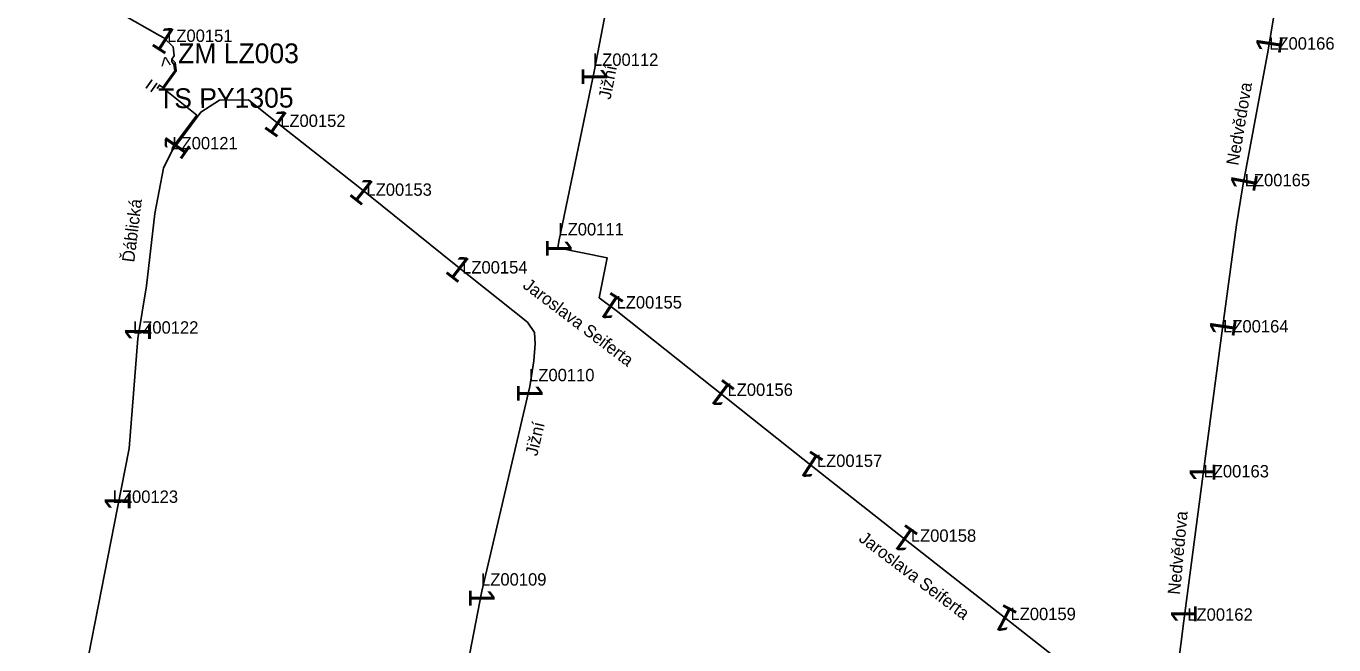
# Model space of a CAD drawing. Extents: x -736540 to -735418, y -1033000 to -1031598.
# Drawn here: x -735899.6 to -735635.6, y -1032780 to -1032655 of the extents above; entities that cross this region are included whole.
import ezdxf

# ---------------------------------------------------------------- set-up
doc = ezdxf.new("R2010")
doc.units = 0
for name, color, linetype in [('ftf_2010', 7, 'Continuous'), ('ftf_2060', 7, 'Continuous'), ('ftf_3010', 7, 'Continuous'), ('ftf_3010_ftf_3010_gtda_3015_gtda_3015_1', 7, 'Continuous'), ('ftf_3150', 7, 'Continuous'), ('ftf_3150_ftf_3150_gtda_3155_gtda_3155_1', 7, 'Continuous'), ('ftf_3160', 7, 'Continuous'), ('ftf_3160_ftf_3160_gtda_3165_gtda_3165_1', 7, 'Continuous'), ('ftf_nu', 7, 'Continuous')]:
    doc.layers.add(name, color=color, linetype=linetype)

msp = doc.modelspace()

# ---------------------------------------------------------------- linework, layer by layer
at = {"layer": 'ftf_2010'}
for points in [[(-735644.46, -1032633.53), (-735648.88, -1032659.9)], [(-735787.44, -1032639.95), (-735782.6, -1032651.92), (-735784.87, -1032663.88)], [(-735899.61, -1032641.58), (-735872.69, -1032656.96)], [(-735872.69, -1032656.96), (-735871.81, -1032657.37), (-735869.91, -1032659.24), (-735869.7, -1032661.03), (-735870.21, -1032661.69)], [(-735648.88, -1032659.9), (-735654.04, -1032687.7)], [(-735870.21, -1032661.69), (-735869.54, -1032662.38), (-735869.3, -1032664.04), (-735871.9, -1032667.64), (-735868.54, -1032670.33), (-735865.18, -1032673.02), (-735870.05, -1032679.55), (-735870.2, -1032680.32)], [(-735792.09, -1032698.53), (-735784.87, -1032663.88)], [(-735870.2, -1032680.32), (-735864.37, -1032672.38), (-735860.55, -1032670), (-735854.75, -1032669.95), (-735849.92, -1032673.73)], [(-735832.6, -1032687.44), (-735849.92, -1032673.73)], [(-735870.2, -1032680.32), (-735871.88, -1032683.75), (-735873.65, -1032692.87), (-735875.34, -1032707.51), (-735877.04, -1032718.13)], [(-735813.21, -1032703.05), (-735832.6, -1032687.44)], [(-735654.04, -1032687.7), (-735655.25, -1032695.17), (-735658.23, -1032717.05)], [(-735792.09, -1032698.53), (-735792.3, -1032699.81), (-735782.31, -1032701.83), (-735783.9, -1032709.89), (-735780.53, -1032712.49)], [(-735813.21, -1032703.05), (-735798.38, -1032714.84), (-735796.99, -1032716.9), (-735796.84, -1032719.22), (-735797.09, -1032722.59), (-735797.94, -1032727.81)], [(-735758.24, -1032730.13), (-735780.53, -1032712.49)], [(-735881.14, -1032752.3), (-735878.85, -1032740.32), (-735877.04, -1032718.13)], [(-735658.23, -1032717.05), (-735662.14, -1032746.47)], [(-735797.94, -1032727.81), (-735807.64, -1032769.14)], [(-735740.2, -1032744.51), (-735758.24, -1032730.13)], [(-735721.18, -1032759.43), (-735740.2, -1032744.51)], [(-735662.14, -1032746.47), (-735665.87, -1032775.1)], [(-735890.13, -1032800.57), (-735887.02, -1032782.2), (-735881.14, -1032752.3)], [(-735721.18, -1032759.43), (-735700.9, -1032775.41)], [(-735814.42, -1032804.25), (-735807.64, -1032769.14)], [(-735681.54, -1032790.25), (-735682.02, -1032790.23), (-735700.9, -1032775.41)], [(-735665.87, -1032775.1), (-735669.61, -1032804.33)]]:
    msp.add_lwpolyline(points, dxfattribs=at)
at = {"layer": 'ftf_2060'}
msp.add_lwpolyline([(-735870.22, -1032661.74), (-735870.17, -1032662.25), (-735869.79, -1032662.71), (-735869.62, -1032664.07), (-735872.02, -1032667.44), (-735872.71, -1032666.96), (-735873.19, -1032667.63)], dxfattribs=at)

# ---------------------------------------------------------------- texts
at = {"layer": 'ftf_3010'}
for rotation, p in [(327.2351, (-735874.64, -1032658.8)), (81.4163, (-735646.41, -1032660.93)), (270, (-735787.47, -1032663.23)), (325.0729, (-735851.94, -1032675.49)), (55.1966, (-735868.44, -1032682.34)), (321.395, (-735834.73, -1032689.06)), (79.2469, (-735651.6, -1032688.82)), (270, (-735794.69, -1032697.88)), (322.2711, (-735815.32, -1032704.71)), (146.9171, (-735778.57, -1032710.66)), (90, (-735874.44, -1032718.77)), (81.6782, (-735655.75, -1032718.07)), (143.1501, (-735756.16, -1032728.44)), (270, (-735800.54, -1032727.17)), (147.1474, (-735738.24, -1032742.68)), (90, (-735659.54, -1032747.12)), (90, (-735878.54, -1032752.95)), (144.8552, (-735719.15, -1032757.67)), (270, (-735810.24, -1032768.5)), (152.5559, (-735699.13, -1032773.4)), (90, (-735663.27, -1032775.75))]:
    msp.add_text('1', height=5.2, rotation=rotation, dxfattribs=at).set_placement(p)
at = {"layer": 'ftf_3010_ftf_3010_gtda_3015_gtda_3015_1'}
for s, p in [('LZ00151', (-735871.15, -1032658.23)), ('LZ00166', (-735648.66, -1032659.79)), ('LZ00152', (-735848.33, -1032675.39)), ('LZ00165', (-735653.6, -1032687.38)), ('LZ00153', (-735830.91, -1032689.3)), ('LZ00154', (-735811.59, -1032704.99)), ('LZ00155', (-735780.42, -1032712.06)), ('LZ00164', (-735657.96, -1032716.9)), ('LZ00156', (-735758.02, -1032729.7)), ('LZ00157', (-735739.98, -1032744.04)), ('LZ00163', (-735661.91, -1032746.16)), ('LZ00158', (-735721.01, -1032759.16)), ('LZ00159', (-735700.89, -1032774.98)), ('LZ00162', (-735665.19, -1032775.1))]:
    msp.add_text(s, height=2.5, dxfattribs=at).set_placement(p)
for s, p in [('LZ00112', (-735785.18, -1032663.06)), ('LZ00121', (-735870.1, -1032679.92)), ('LZ00111', (-735792.15, -1032697.31)), ('LZ00122', (-735878.04, -1032717.13)), ('LZ00110', (-735798.07, -1032726.74)), ('LZ00123', (-735882.14, -1032751.3)), ('LZ00109', (-735807.77, -1032768.01))]:
    msp.add_text(s, height=2.5, rotation=0, dxfattribs=at).set_placement(p)
at = {"layer": 'ftf_3150'}
msp.add_text('>', height=2.7, rotation=97.9419, dxfattribs=at).set_placement((-735870.03, -1032663.03))
at = {"layer": 'ftf_3150_ftf_3150_gtda_3155_gtda_3155_1'}
msp.add_text('ZM LZ003', height=4, rotation=359.9641, dxfattribs=at).set_placement((-735868.93, -1032662.52))
at = {"layer": 'ftf_3160'}
msp.add_text('=', height=3.3, rotation=54.532, dxfattribs=at).set_placement((-735873.77, -1032669.04))
at = {"layer": 'ftf_3160_ftf_3160_gtda_3165_gtda_3165_1'}
msp.add_text('TS PY1305', height=4, rotation=0.2894, dxfattribs=at).set_placement((-735872.97, -1032671.62))
at = {"layer": 'ftf_nu'}
for s, rotation, p in [('Jižní', 78.9873, (-735781.64, -1032669.98)), ('Nedvědova', 80.47, (-735654.9, -1032683.29)), ('Ďáblická', 82.9721, (-735877.8, -1032702.82)), ('Jaroslava Seiferta', 322.8622, (-735799.53, -1032707.74)), ('Jižní', 76.9129, (-735796.45, -1032741.99)), ('Nedvědova', 84.6553, (-735666.68, -1032769.92)), ('Jaroslava Seiferta', 322.8622, (-735731.71, -1032758.87))]:
    msp.add_text(s, height=2.5, rotation=rotation, dxfattribs=at).set_placement(p)

doc.saveas('drawing.dxf')
